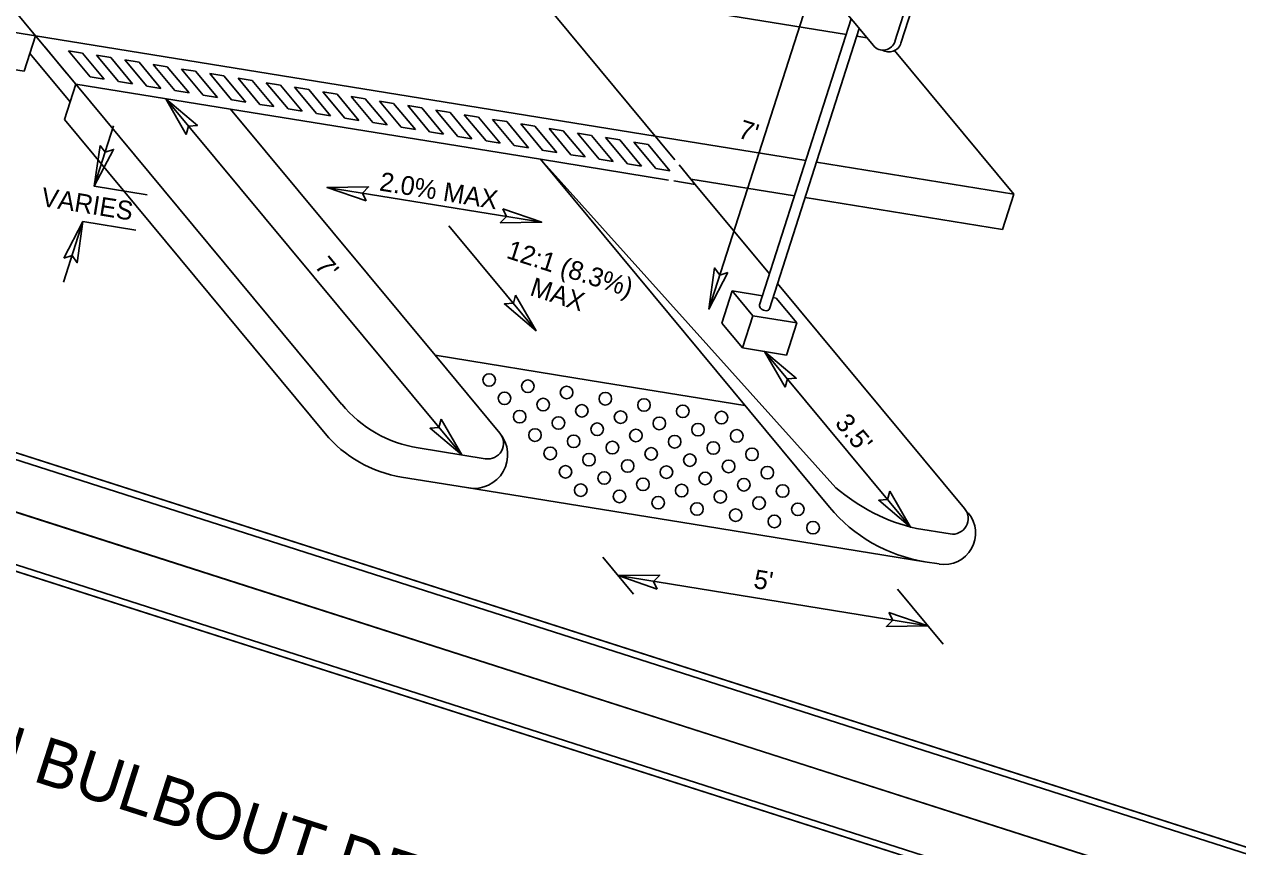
# Model space of a CAD drawing. Extents: x 928111 to 937215, y 684320 to 686530.
# Drawn here: x 933651.39 to 933670.73, y 684695.17 to 684708.27 of the extents above; entities that cross this region are included whole.
import ezdxf

# ---------------------------------------------------------------- set-up
doc = ezdxf.new("R2010")
doc.units = 0
for name, color, linetype in [('Exist Roads EOP', 7, 'Continuous'), ('Prop Conc 5in Monolithic Keyed In Island', 7, 'Continuous'), ('Prop Conc Curb 8in x 6in', 7, 'Continuous'), ('Prop Dimension', 7, 'Continuous'), ('Prop DSN Text', 7, 'Continuous'), ('Prop Terminator CELL', 7, 'Continuous'), ('Sheet Clip Boundary CELL', 7, 'Continuous'), ('Sheet Cutting Line CELL', 7, 'Continuous'), ('Sheet Layout Plan Border', 7, 'Continuous'), ('Sheet Plan CELL', 7, 'Continuous'), ('Sheet Plan Layout CELL', 7, 'Continuous'), ('Sheet Plot Border Inside CELL', 7, 'Continuous'), ('Sheet Plot Border Outside CELL', 7, 'Continuous')]:
    doc.layers.add(name, color=color, linetype=linetype)

msp = doc.modelspace()

# ---------------------------------------------------------------- linework, layer by layer
at = {"layer": 'Exist Roads EOP'}
for p, q in [((933641.435, 684709.728), (933651.572, 684708.089)), ((933641.254, 684709.164), (933651.391, 684707.524)), ((933659.416, 684708.933), (933664.489, 684708.112)), ((933664.657, 684708.085), (933664.816, 684708.059)), ((933667.159, 684705.568), (933665.259, 684707.854)), ((933661.444, 684706.492), (933663.845, 684706.104)), ((933664.014, 684706.076), (933667.159, 684705.568)), ((933662.014, 684705.806), (933663.664, 684705.539)), ((933663.833, 684705.512), (933666.978, 684705.003)), ((933667.159, 684705.568), (933666.978, 684705.003)), ((933667.004, 684705.086), (933667.004, 684705.086))]:
    msp.add_line(p, q, dxfattribs=at)
at = {"layer": 'Prop Conc 5in Monolithic Keyed In Island'}
for p, q in [((933665.813, 684709.712), (933665.264, 684708.001)), ((933665.907, 684709.682), (933665.358, 684707.971)), ((933661.759, 684706.113), (933659.416, 684708.933)), ((933664.92, 684707.934), (933664.157, 684708.853)), ((933663.108, 684703.804), (933664.568, 684708.358)), ((933663.264, 684703.737), (933664.696, 684708.204)), ((933651.572, 684708.089), (933651.391, 684707.524)), ((933652.211, 684707.32), (933651.572, 684708.089)), ((933652.12, 684707.037), (933651.481, 684707.806)), ((933652.065, 684707.495), (933651.718, 684707.913)), ((933652.441, 684707.434), (933652.093, 684707.853)), ((933652.093, 684707.853), (933652.318, 684707.816)), ((933652.666, 684707.398), (933652.318, 684707.816)), ((933652.891, 684707.362), (933652.544, 684707.78)), ((933652.544, 684707.78), (933652.769, 684707.743)), ((933653.116, 684707.325), (933652.769, 684707.743)), ((933653.342, 684707.289), (933652.994, 684707.707)), ((933652.994, 684707.707), (933653.22, 684707.67)), ((933653.567, 684707.252), (933653.22, 684707.67)), ((933653.792, 684707.216), (933653.445, 684707.634)), ((933653.445, 684707.634), (933653.67, 684707.597)), ((933654.018, 684707.179), (933653.67, 684707.597)), ((933652.441, 684707.434), (933652.666, 684707.398)), ((933654.243, 684707.143), (933653.895, 684707.561)), ((933653.895, 684707.561), (933654.121, 684707.525)), ((933654.468, 684707.106), (933654.121, 684707.525)), ((933654.693, 684707.07), (933654.346, 684707.488)), ((933654.346, 684707.488), (933654.571, 684707.452)), ((933654.919, 684707.034), (933654.571, 684707.452)), ((933655.144, 684706.997), (933654.797, 684707.415)), ((933654.797, 684707.415), (933655.022, 684707.379)), ((933655.369, 684706.961), (933655.022, 684707.379)), ((933652.211, 684707.32), (933654.679, 684706.92)), ((933652.891, 684707.362), (933653.116, 684707.325)), ((933653.342, 684707.289), (933653.567, 684707.252)), ((933653.792, 684707.216), (933654.018, 684707.179)), ((933655.595, 684706.924), (933655.247, 684707.342)), ((933655.247, 684707.342), (933655.472, 684707.306)), ((933655.82, 684706.888), (933655.472, 684707.306)), ((933656.045, 684706.851), (933655.698, 684707.269)), ((933655.698, 684707.269), (933655.923, 684707.233)), ((933656.27, 684706.815), (933655.923, 684707.233)), ((933656.496, 684706.779), (933656.148, 684707.197)), ((933656.148, 684707.197), (933656.374, 684707.16)), ((933654.243, 684707.143), (933654.468, 684707.106)), ((933654.693, 684707.07), (933654.703, 684707.069)), ((933654.703, 684707.069), (933654.919, 684707.034)), ((933655.144, 684706.997), (933655.369, 684706.961)), ((933656.721, 684706.742), (933656.374, 684707.16)), ((933656.946, 684706.706), (933656.599, 684707.124)), ((933656.599, 684707.124), (933656.824, 684707.087)), ((933657.172, 684706.669), (933656.824, 684707.087)), ((933657.397, 684706.633), (933657.05, 684707.051)), ((933657.05, 684707.051), (933657.275, 684707.014)), ((933657.622, 684706.596), (933657.275, 684707.014)), ((933655.595, 684706.924), (933655.82, 684706.888)), ((933656.045, 684706.851), (933656.27, 684706.815)), ((933657.847, 684706.56), (933657.5, 684706.978)), ((933657.5, 684706.978), (933657.725, 684706.942)), ((933658.073, 684706.523), (933657.725, 684706.942)), ((933658.298, 684706.487), (933657.951, 684706.905)), ((933657.951, 684706.905), (933658.119, 684706.878)), ((933658.119, 684706.878), (933658.176, 684706.869)), ((933658.523, 684706.451), (933658.176, 684706.869)), ((933658.749, 684706.414), (933658.401, 684706.832)), ((933658.401, 684706.832), (933658.627, 684706.796)), ((933658.974, 684706.378), (933658.627, 684706.796)), ((933652.03, 684706.755), (933656.184, 684701.755)), ((933656.496, 684706.779), (933656.721, 684706.742)), ((933656.946, 684706.706), (933657.171, 684706.669)), ((933657.172, 684706.669), (933657.171, 684706.669)), ((933657.622, 684706.596), (933657.397, 684706.633)), ((933659.199, 684706.341), (933658.852, 684706.759)), ((933658.852, 684706.759), (933659.077, 684706.723)), ((933659.424, 684706.305), (933659.077, 684706.723)), ((933659.65, 684706.268), (933659.302, 684706.686)), ((933659.302, 684706.686), (933659.528, 684706.65)), ((933659.875, 684706.232), (933659.528, 684706.65)), ((933660.1, 684706.195), (933659.753, 684706.614)), ((933659.753, 684706.614), (933659.978, 684706.577)), ((933658.073, 684706.523), (933657.847, 684706.56)), ((933658.523, 684706.451), (933658.298, 684706.487)), ((933658.974, 684706.378), (933658.749, 684706.414)), ((933660.326, 684706.159), (933659.978, 684706.577)), ((933660.551, 684706.123), (933660.204, 684706.541)), ((933660.204, 684706.541), (933660.429, 684706.504)), ((933660.776, 684706.086), (933660.429, 684706.504)), ((933661.001, 684706.05), (933660.654, 684706.468)), ((933660.654, 684706.468), (933660.879, 684706.431)), ((933661.227, 684706.013), (933660.879, 684706.431)), ((933659.424, 684706.305), (933659.199, 684706.341)), ((933659.639, 684706.27), (933659.875, 684706.232)), ((933661.452, 684705.977), (933661.105, 684706.395)), ((933661.105, 684706.395), (933661.33, 684706.359)), ((933661.677, 684705.94), (933661.33, 684706.359)), ((933659.615, 684706.122), (933661.655, 684705.792)), ((933660.1, 684706.195), (933660.326, 684706.159)), ((933660.551, 684706.123), (933660.776, 684706.086)), ((933661.001, 684706.05), (933661.227, 684706.013)), ((933662.083, 684705.723), (933661.823, 684706.036)), ((933661.452, 684705.977), (933661.677, 684705.94)), ((933661.74, 684705.778), (933662.083, 684705.723)), ((933662.67, 684704.025), (933662.506, 684703.513)), ((933662.67, 684704.025), (933663.154, 684703.947)), ((933663, 684703.629), (933662.67, 684704.025)), ((933663.322, 684703.92), (933663.372, 684703.912)), ((933663.701, 684703.515), (933663.372, 684703.912)), ((933662.506, 684703.513), (933662.836, 684703.117)), ((933663, 684703.629), (933662.836, 684703.117)), ((933663, 684703.629), (933663.701, 684703.515)), ((933663.701, 684703.515), (933663.537, 684703.003)), ((933662.836, 684703.117), (933663.537, 684703.003)), ((933657.667, 684701.523), (933658.737, 684701.35)), ((933657.403, 684701.059), (933658.437, 684700.892))]:
    msp.add_line(p, q, dxfattribs=at)
for centre, radius, start, end in [((933665.074, 684708.062), 0.2, 219.7204, 342.2273), ((933665.168, 684708.032), 0.2, 238.0075, 342.2273), ((933666.282, 684703.163), 3.001, 229.2707, 256.9687)]:
    msp.add_arc(centre, radius, start, end, dxfattribs=at)
msp.add_ellipse((933663.186, 684703.77), major_axis=(0.0779, -0.0334), ratio=0.646274, start_param=3.141593, end_param=6.406403, dxfattribs=at)
at = {"layer": 'Prop Conc Curb 8in x 6in'}
for p, q in [((933651.572, 684708.089), (933649.544, 684710.529)), ((933651.572, 684708.089), (933661.444, 684706.492)), ((933652.211, 684707.32), (933652.03, 684706.755)), ((933656.448, 684702.219), (933652.211, 684707.32)), ((933657.937, 684702.999), (933654.679, 684706.92)), ((933654.679, 684706.92), (933657.147, 684706.521)), ((933659.615, 684706.122), (933657.147, 684706.521)), ((933664.219, 684700.581), (933659.615, 684706.122)), ((933664.324, 684700.888), (933659.615, 684706.122)), ((933663.266, 684704.298), (933662.083, 684705.723)), ((933666.373, 684700.559), (933663.394, 684704.144)), ((933657.937, 684702.999), (933658.969, 684701.756)), ((933657.937, 684702.999), (933660.405, 684702.6)), ((933662.873, 684702.2), (933660.405, 684702.6)), ((933658.437, 684700.892), (933662.051, 684700.307)), ((933662.051, 684700.307), (933665.742, 684699.71)), ((933665.606, 684700.239), (933666.141, 684700.152)), ((933665.742, 684699.71), (933665.968, 684699.674))]:
    msp.add_line(p, q, dxfattribs=at)
for centre in [(933658.798, 684702.606), (933659.415, 684702.506), (933659.042, 684702.314), (933660.032, 684702.407), (933660.649, 684702.307), (933659.658, 684702.214), (933660.275, 684702.114), (933661.266, 684702.207), (933661.883, 684702.107), (933659.285, 684702.021), (933659.902, 684701.921), (933660.892, 684702.014), (933661.509, 684701.914), (933662.5, 684702.007), (933659.528, 684701.728), (933660.519, 684701.821), (933661.136, 684701.722), (933662.126, 684701.815), (933662.743, 684701.715), (933660.145, 684701.629), (933660.762, 684701.529), (933661.753, 684701.622), (933662.369, 684701.522), (933659.771, 684701.436), (933660.388, 684701.336), (933661.379, 684701.429), (933661.996, 684701.329), (933662.986, 684701.422), (933660.014, 684701.143), (933661.005, 684701.236), (933661.622, 684701.137), (933662.613, 684701.229), (933663.23, 684701.13), (933660.631, 684701.044), (933661.248, 684700.944), (933662.239, 684701.037), (933662.856, 684700.937), (933660.257, 684700.851), (933660.874, 684700.751), (933661.865, 684700.844), (933662.482, 684700.744), (933663.473, 684700.837), (933661.491, 684700.651), (933662.108, 684700.551), (933663.099, 684700.644), (933663.716, 684700.545), (933662.725, 684700.452), (933663.342, 684700.352), (933663.959, 684700.252)]:
    msp.add_circle(centre, 0.1, dxfattribs=at)
for centre, radius, start, end in [((933657.987, 684703.497), 2, 219.7204, 260.8123), ((933657.722, 684703.033), 2, 219.7204, 260.8123), ((933658.558, 684701.414), 0.535, 260.8123, 39.7204), ((933658.777, 684701.597), 0.25, 260.8123, 39.7204), ((933666.142, 684702.178), 2.5, 219.7204, 260.8123), ((933666.048, 684700.167), 0.5, 260.8123, 39.7204), ((933666.181, 684700.399), 0.25, 260.8123, 39.7204)]:
    msp.add_arc(centre, radius, start, end, dxfattribs=at)
at = {"layer": 'Prop Dimension'}
for p, q in [((933662.299, 684703.736), (933663.986, 684708.999)), ((933658.361, 684701.411), (933653.645, 684707.088)), ((933652.815, 684706.656), (933652.507, 684705.693)), ((933652.507, 684705.693), (933653.35, 684705.557)), ((933656.216, 684705.673), (933659.637, 684705.119)), ((933652.326, 684705.129), (933652.017, 684704.166)), ((933652.326, 684705.129), (933653.169, 684704.992)), ((933659.547, 684703.39), (933658.157, 684705.064)), ((933665.511, 684700.263), (933663.186, 684703.06)), ((933661.097, 684699.195), (933660.611, 684699.781)), ((933660.854, 684699.488), (933665.79, 684698.69)), ((933665.304, 684699.275), (933666.033, 684698.397))]:
    msp.add_line(p, q, dxfattribs=at)
at = {"layer": 'Prop Terminator CELL'}
for points in [[(933653.973, 684706.518), (933653.645, 684707.088), (933654.15, 684706.66), (933654.008, 684706.65)], [(933652.598, 684706.344), (933652.507, 684705.693), (933652.815, 684706.279), (933652.68, 684706.235)], [(933656.838, 684705.459), (933656.216, 684705.673), (933656.878, 684705.682), (933656.778, 684705.582)], [(933659.015, 684705.333), (933659.637, 684705.119), (933658.975, 684705.11), (933659.075, 684705.21)], [(933652.022, 684704.546), (933652.326, 684705.129), (933652.236, 684704.473), (933652.152, 684704.587)], [(933662.603, 684704.319), (933662.299, 684703.736), (933662.388, 684704.392), (933662.473, 684704.278)], [(933659.219, 684703.96), (933659.547, 684703.39), (933659.042, 684703.818), (933659.184, 684703.828)], [(933663.514, 684702.49), (933663.186, 684703.06), (933663.691, 684702.633), (933663.55, 684702.623)], [(933658.033, 684701.98), (933658.361, 684701.411), (933657.856, 684701.838), (933657.998, 684701.848)], [(933665.182, 684700.832), (933665.511, 684700.263), (933665.006, 684700.69), (933665.147, 684700.7)], [(933661.476, 684699.274), (933660.854, 684699.488), (933661.515, 684699.498), (933661.415, 684699.397)], [(933665.168, 684698.903), (933665.79, 684698.69), (933665.128, 684698.68), (933665.228, 684698.78)]]:
    msp.add_lwpolyline(points, close=True, dxfattribs=at)
at = {"layer": 'Sheet Clip Boundary CELL'}
for points in [[(933632.873, 684707.339), (933686.201, 684690.246), (933696.439, 684722.185), (933689.23, 684724.496), (933691.812, 684732.552), (933645.693, 684747.335)], [(933619.504, 684665.63), (933672.831, 684648.536), (933683.069, 684680.476), (933675.86, 684682.787), (933678.442, 684690.842), (933632.324, 684705.625)]]:
    msp.add_lwpolyline(points, close=True, dxfattribs=at)
at = {"layer": 'Sheet Cutting Line CELL'}
for p, q in [((933624.352, 684709.125), (933688.478, 684688.57)), ((933688.478, 684688.57), (933624.352, 684709.125))]:
    msp.add_line(p, q, dxfattribs=at)
at = {"layer": 'Sheet Layout Plan Border'}
for points in [[(933632.873, 684707.339), (933686.201, 684690.246), (933696.439, 684722.185), (933689.23, 684724.496), (933691.812, 684732.552), (933645.693, 684747.335)], [(933619.504, 684665.63), (933672.831, 684648.536), (933683.069, 684680.476), (933675.86, 684682.787), (933678.442, 684690.842), (933632.324, 684705.625)]]:
    msp.add_lwpolyline(points, close=True, dxfattribs=at)
at = {"layer": 'Sheet Plan CELL'}
for points in [[(933700.927, 684729.63), (933643.789, 684747.945), (933630.969, 684707.95), (933688.106, 684689.635)], [(933630.969, 684707.95), (933643.787, 684747.945), (933693.306, 684732.074), (933691.474, 684726.358), (933699.093, 684723.915), (933688.106, 684689.635)], [(933687.557, 684687.921), (933630.419, 684706.236), (933617.599, 684666.24), (933674.736, 684647.926)], [(933617.599, 684666.24), (933630.418, 684706.235), (933679.936, 684690.364), (933678.104, 684684.648), (933685.724, 684682.205), (933674.736, 684647.926)]]:
    msp.add_lwpolyline(points, close=True, dxfattribs=at)
at = {"layer": 'Sheet Plan Layout CELL'}
for points in [[(933643.787, 684747.945), (933630.969, 684707.95), (933688.105, 684689.635), (933698.343, 684721.575), (933689.23, 684724.496), (933691.812, 684732.552)], [(933630.418, 684706.235), (933617.599, 684666.24), (933674.736, 684647.926), (933684.973, 684679.865), (933675.86, 684682.787), (933678.442, 684690.842)]]:
    msp.add_lwpolyline(points, close=True, dxfattribs=at)
at = {"layer": 'Sheet Plot Border Inside CELL'}
for points in [[(933625.091, 684709.728), (933688.551, 684689.388), (933701.432, 684729.573), (933637.973, 684749.914)], [(933611.722, 684668.018), (933675.181, 684647.678), (933688.063, 684687.863), (933624.603, 684708.204)]]:
    msp.add_lwpolyline(points, close=True, dxfattribs=at)
at = {"layer": 'Sheet Plot Border Outside CELL'}
for points in [[(933624.352, 684709.125), (933688.478, 684688.57), (933701.848, 684730.28), (933637.722, 684750.835)], [(933610.982, 684667.415), (933675.109, 684646.86), (933688.478, 684688.57), (933624.352, 684709.125)]]:
    msp.add_lwpolyline(points, close=True, dxfattribs=at)

# ---------------------------------------------------------------- texts
at = {"layer": 'Prop DSN Text'}
for s, height, rotation, p in [("7'", 0.3, 342.2273, (933662.747, 684706.473)), ('2.0% MAX', 0.3, 350.8123, (933657.037, 684705.627)), ('VARIES', 0.3, 350.8123, (933651.646, 684705.38)), ('12:1 (8.3%)', 0.3, 342.2273, (933659.057, 684704.554)), ("7'", 0.3, 309.7204, (933656.004, 684704.417)), ('MAX', 0.3, 342.2273, (933659.43, 684703.962)), ("3.5'", 0.3, 309.7204, (933664.294, 684701.913)), ("5'", 0.3, 350.8123, (933662.998, 684699.293)), ('PEDESTRIAN BULBOUT DETAIL (CONT.)', 0.75, 342.2273, (933645.138, 684698.264))]:
    msp.add_text(s, height=height, rotation=rotation, dxfattribs=at).set_placement(p)

doc.saveas('drawing.dxf')
